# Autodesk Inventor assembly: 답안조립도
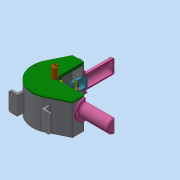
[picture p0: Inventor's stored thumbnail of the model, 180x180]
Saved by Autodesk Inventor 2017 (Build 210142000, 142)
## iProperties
Part Number: 답안조립도
Material: 일반
Document SubType Name: Assembly
Designer: MRC
Mass: 3748.68 g
Surface Area: 4101.78 cm^2
Volume: 1119.43 cm^3
Density: 3.34872 g/cm^3
Author: MRC
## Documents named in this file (13)
- C:\Users\MRC\Desktop\611109V1003\답안조립도.iam
- C:\Users\MRC\Desktop\611109V1003\본체.ipt
- C:\Users\MRC\Desktop\611109V1003\너트 M3.ipt
- C:\Users\MRC\Desktop\611109V1003\베어링 20 x 37 x 9.ipt
- C:\Users\MRC\Desktop\611109V1003\볼트 M3 x 12.ipt
- C:\Users\MRC\Desktop\611109V1003\실린더.ipt
- C:\Users\MRC\Desktop\611109V1003\앞커버.ipt
- C:\Users\MRC\Desktop\611109V1003\축.ipt
- C:\Users\MRC\Desktop\611109V1003\측정게이지.ipt
- C:\Users\MRC\Desktop\611109V1003\커넥팅로드 캡.ipt
- C:\Users\MRC\Desktop\611109V1003\커넥팅로드.ipt
- C:\Users\MRC\Desktop\611109V1003\피스톤 핀.ipt
- C:\Users\MRC\Desktop\611109V1003\피스톤.ipt
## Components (4 placed, 2 different names)
1. 피스톤 핀:1
2. 피스톤:1
3. 피스톤:2
4. 피스톤 핀:2
